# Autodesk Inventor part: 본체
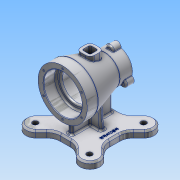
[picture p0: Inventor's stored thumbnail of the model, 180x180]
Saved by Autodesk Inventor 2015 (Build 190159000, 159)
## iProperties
Created: 2018-03
Part Number: 본체
Material: 알루미늄 6061
Document SubType Name: Modeling
Designer: SCD-A03
Density: 2.7 g/cm^3
Appearance: 알루미늄 - 평지
Mass: 1014.9 g
Surface Area: 858.039 cm^2
Volume: 375.89 cm^3
Author: SCD-A03
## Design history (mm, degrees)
sketch "스케치2"
  geometry: C1 r 45 at (0, 0); 1 further point
  constraints: 1 centre point, 1 coincident
  dimensions: "d3" = 90 diameter of C1
extrude "돌출2" new body sketch "스케치2" distance "d4" = 20; taper "d5" = 0 deg
node "작업 평면3"
sketch "스케치3"
  geometry: C1 r 27.5 at (0, 0); 1 further point
  constraints: 1 centre point, 1 coincident
  dimensions: "d9" = 55 diameter of C1
extrude "돌출3" join sketch "스케치3" distance "d10" = 23; taper "d11" = 0 deg
sketch "스케치4"
  geometry: L1 (0, -45)-(-20, -45) reference; L2 (-20, -45)-(-20, 45) reference; L3 (-20, 45)-(0, 45) reference; L4 (0, 45)-(0, -45) reference; L5 (57, 27.5)-(80, 27.5) reference; L6 (80, 27.5)-(80, -27.5) reference; L7 (80, -27.5)-(57, -27.5) reference; L8 (57, -27.5)-(57, 27.5) reference; L9 (0, 45)-(57, 27.5); L10 (57, 27.5)-(57, 0); L11 (57, 0)-(0, 0); L12 (0, 45)-(0, 0)
  constraints: 8 end point, 1 collinear, 1 midpoint, 1 perpendicular
revolve "회전1" sketch "스케치4" stored, may be unused: angle "d12" = 90 deg
node "작업 평면4"
sketch "스케치5"
  geometry: L1 (-12.5, 17.5)-(12.5, 17.5); L2 (12.5, 17.5)-(12.5, 42.5); L3 (12.5, 42.5)-(-12.5, 42.5); L4 (-12.5, 42.5)-(-12.5, 17.5); L5 (-12.5, 17.5)-(12.5, 42.5); L6 (12.5, 17.5)-(-12.5, 42.5); L7 (-45, -20)-(45, -20) reference; 2 further points
  constraints: 12 end point, 2 midpoint, 2 parallel, 1 horizontal, 1 perpendicular
  dimensions: "d14" = 25 distance of L3.end L2.end; "d15" = 25 distance of L2.end L1.end; "d218" = 50 distance from line of point (0, 30) L7
extrude "돌출4" join sketch "스케치5" stored distance "d16" = 23; taper "d17" = 0 deg
sketch "스케치6"
  geometry: L1 (57, -27.5)-(0, -45) reference; L2 (0, -45)-(-20, -45) reference; L3 (-20, -45)-(-20, 45) reference; L4 (-20, 45)-(0, 45) reference; L5 (0, 45)-(17.5, 39.627) reference; L6 (17.5, 39.627)-(17.5, 45) reference; L7 (17.5, 45)-(42.5, 45) reference; L8 (42.5, 45)-(42.5, 31.952) reference; L9 (42.5, 31.952)-(57, 27.5) reference; L10 (57, 27.5)-(80, 27.5) reference; L11 (80, 27.5)-(80, -27.5) reference; L12 (80, -27.5)-(57, -27.5) reference; L13 (-20, 0)-(80, 0); L14 (-20, 35)-(3, 35); L15 (3, 35)-(3, 26); L16 (3, 26)-(50, 26); L17 (50, 26)-(50, 20); L18 (50, 20)-(80, 20); 1 further point
  constraints: 12 end point, 4 perpendicular, 2 midpoint, 2 point on line, 1 horizontal
  dimensions: "d18" = 23 distance of L14.start L14.end; "d19" = 47 distance of L15.end L16.end; "d20" = 35 distance between parallel lines of L13 L14; "d21" = 26 distance between parallel lines of L13 L16; "d22" = 20 distance between parallel lines of L13 L18
revolve "회전2" sketch "스케치6" stored, may be unused: angle "d23" = 90 deg
sketch "스케치7"
  geometry: L1 (-7.5, 22.5)-(7.5, 22.5); L2 (7.5, 22.5)-(7.5, 37.5); L3 (7.5, 37.5)-(-7.5, 37.5); L4 (-7.5, 37.5)-(-7.5, 22.5); L5 (-7.5, 22.5)-(7.5, 37.5); L6 (7.5, 22.5)-(-7.5, 37.5); L7 (-45, -20)-(45, -20) reference; 2 further points
  constraints: 12 end point, 2 midpoint, 2 parallel, 1 horizontal, 1 perpendicular
  dimensions: "d24" = 15 distance of L3.end L2.end; "d25" = 15 distance of L2.end L1.end; "d219" = 50 distance from line of L7 point (0, 30)
extrude "돌출5" cut sketch "스케치7" stored distance "d26" = 23; taper "d27" = 0 deg
node "작업 평면5"
sketch "스케치10"
  geometry: C1 r 35 at (0, 0) reference; 1 further point
  dimensions: "d59" = 40 distance of point (0, 40) C1.centre
hole "구멍2" sketch "스케치10" at (0, 40) diameter "d60" = 3.242; stored, may be unused: countersink angle "d64" = 90 deg, drill point angle "d66" = 118 deg; dims "d61" = 9, "d62" = 4, "d63" = 2, "d65" = 11
sketch "스케치11"
  geometry: C1 r 7 at (0, -27.5); 1 further point
  constraints: 1 centre point, 1 vertical alignment, 1 other
  dimensions: "d70" = 14 diameter of C1
extrude "돌출8" join sketch "스케치11" distance "d71" = 15; taper "d72" = 0 deg
hole "구멍3" diameter "d78" = 3.242; stored, may be unused: countersink angle "d82" = 90 deg, drill point angle "d84" = 118 deg; dims "d76" = 10, "d77" = 10, "d79" = 9, "d80" = 4, "d81" = 2, "d83" = 11
fillet "모깎기1" dims "d88" = 8
fillet "모깎기2" dims "d89" = 3
fillet "모깎기3" dims "d90" = 3
fillet "모깎기4" dims "d91" = 3
node "작업 평면7"
fillet "모깎기8" dims "d135" = 3
fillet "모깎기9" dims "d136" = 1
fillet "모깎기10" dims "d137" = 3
chamfer "모따기5" distance "d143" = 1; stored, may be unused: second distance "d144" = 2, angle "d145" = 45 deg
node "작업 평면10"
sketch "스케치19" dims "d24" = 15, "d25" = 15, "d219" = 50
  geometry: L1 (-26, 47)-(26, 47) reference; L2 (7.5, 25.5)-(7.5, 34.5) reference; L3 (4.5, 37.5)-(-4.5, 37.5) reference; L4 (-7.5, 34.5)-(-7.5, 25.5) reference; L5 (-4.5, 22.5)-(4.5, 22.5) reference; L6 (26, 6)-(-26, 6) reference; L7 (-7.5, 30)-(0, 30); L8 (0, 30)-(0, 37.5); L9 (-45, -15)-(45, -15); L10 (45, -15)-(45, 75); L11 (45, 75)-(-45, 75); L12 (-45, 75)-(-45, -15); L13 (-45, -15)-(45, 75); L14 (45, -15)-(-45, 75); L15 (0, 30)-(49.497, 79.497); L16 (45, -15)-(-45, 75); L17 (45, 75)-(-45, -15); L18 (-45, 75)-(45, -15); L19 (49.497, 79.497)-(31.497, 97.497); L20 (-49.497, 79.497)-(-36.77, 92.225); L21 (-36.77, 92.225)-(62.225, -6.77); L22 (-62.225, 66.77)-(36.77, -32.225); L23 (-36.77, -32.225)-(62.225, 66.77); L24 (-62.225, -6.77)-(36.77, 92.225); L25 (4.5, 22.5)-(-4.5, 22.5) reference; L26 (-7.5, 25.5)-(-7.5, 34.5) reference; L27 (-4.5, 37.5)-(4.5, 37.5) reference; L28 (7.5, 34.5)-(7.5, 25.5) reference; A1 r 18 centre (49.497, 79.497) between (62.225, 66.77) and (36.77, 92.225); A2 r 18 centre (-49.497, 79.497) between (-36.77, 92.225) and (-62.225, 66.77); A3 r 18 centre (-49.497, -19.497) between (-36.77, -32.225) and (-62.225, -6.77); A4 r 18 centre (49.497, -19.497) between (62.225, -6.77) and (36.77, -32.225); 1 further point
  constraints: 36 end point, 8 point on circle, 4 centre point, 4 midpoint, 2 horizontal, 2 parallel, 2 perpendicular, 2 tangent, 1 coincident, 1 point on line, 25 other
  dimensions: "d178" = 90 distance of L11.end L10.end; "d179" = 90 distance of L10.end L9.end; "d180" = 70 distance of L7.end L15.end; "d181" = 36 diameter of A1; "d184" = 360 deg dimension on L7.end L19.start (derived)
extrude "돌출14" join sketch "스케치19" distance "d186" = 12; taper "d187" = 0 deg
sketch "스케치20"
  geometry: L1 (-4, -7)-(4, -7); L2 (4, -7)-(4, 67); L3 (4, 67)-(-4, 67); L4 (-4, 67)-(-4, -7); L5 (-4, -7)-(4, 67); L6 (4, -7)-(-4, 67); L7 (-19.544, -15)-(19.544, -15) reference; 2 further points
  constraints: 12 end point, 2 midpoint, 2 parallel, 1 horizontal, 1 perpendicular
  dimensions: "d188" = 8 distance of L3.end L2.end; "d189" = 74 distance of L2.end L1.end; "d220" = 8 distance between parallel lines of L1 L7
extrude "돌출15" join sketch "스케치20" stored distance "d190" = 12; taper "d191" = 0 deg
node "작업 평면11"
sketch "스케치21"
  geometry: L1 (-3.5, -94.895)-(-3.5, -115) reference; L2 (-3.5, -115)-(-8.5, -115) reference; L3 (-8.5, -115)-(-8.5, -103.536) reference; L4 (0, -34.435)-(0, 0) reference; L5 (0, 0)-(-41, 0) reference; L6 (-41, 0)-(-41, 12) reference; L7 (-41, 12)-(49, 12) reference; L8 (49, 12)-(49, 0) reference; L9 (49, 0)-(8, 0) reference; L10 (8, 0)-(8, -34.435) reference; L11 (16.5, -103.536)-(16.5, -115) reference; L12 (16.5, -115)-(11.5, -115) reference; L13 (11.5, -115)-(11.5, -94.895) reference; L14 (4, 6)-(4, -41.14); L15 (4, 6)-(28, 6); L16 (4, 6)-(28, 6); L17 (28, 6)-(28, 0); L18 (28, 6)-(42.578, 6); L19 (28, 0)-(24.322, -42.041); L20 (28, 0)-(70.201, 0); L21 (24.322, -42.041)-(4, -41.14); L22 (4, 6)-(-20, 6); L23 (-20, 0)-(-16.322, -42.041); L24 (-20, 6)-(-20, 0); L25 (-16.322, -42.041)-(4, -41.14); L26 (4, 6)-(-20, 4.199); L27 (4, 6)-(28, 3); A1 r 26 centre (4, -70) between (11.5, -94.895) and (-3.5, -94.895) reference; A2 r 35.789 centre (4, -70) between (0, -34.435) and (-8.5, -103.536) reference; A3 r 35.789 centre (4, -70) between (16.5, -103.536) and (8, -34.435) reference; 3 further points
  constraints: 28 end point, 4 horizontal, 4 symmetric about line, 2 equal length, 2 point on line, 1 midpoint, 1 vertical
  dimensions: "d192" = 24 distance of L14.start L15.end; "d193" = 0 distance between parallel lines of L15 L16 (derived); "d194" = 90 deg angle of L17 L18; "d195" = 95 deg angle of L19 L20
extrude "돌출16" join sketch "스케치21" stored distance "d196" = 8; taper "d197" = 0 deg
fillet "모깎기15" dims "d198" = 3
fillet "모깎기16" dims "d199" = 3
sketch "스케치22"
  geometry: A1 r 15 centre (-49.497, -20.545) between (-60.104, -9.939) and (-38.891, -31.152) reference; A2 r 15 centre (49.497, -20.545) between (38.891, -31.152) and (60.104, -9.939) reference; A3 r 15 centre (49.497, 78.45) between (60.104, 67.843) and (38.891, 89.056) reference; A4 r 15 centre (-49.497, 78.45) between (-38.891, 89.056) and (-60.104, 67.843) reference; 1 further point
hole "구멍5" sketch "스케치22" at (49.497, 78.45), (-49.497, 78.45), (49.497, -20.545), (-49.497, -20.545) diameter "d203" = 10; stored, may be unused: countersink angle "d207" = 90 deg, drill point angle "d209" = 118 deg; dims "d204" = 6, "d205" = 4, "d206" = 2, "d208" = 8
sketch "스케치23"
  geometry: L1 (19.544, 75)-(-19.544, 75) reference; 2 further points
  constraints: 1 other
  dimensions: "d216" = 45 distance from line of L1 point (35, 30); "d217" = 35 horizontal distance of point (0, 0) point (35, 30)
feature "엠보싱2" sketch "스케치23" dims "d3" = 90, "d13" = 45, "d210" = 0.5, "d211" = 0
fillet "모깎기17" dims "d212" = 25
chamfer "모따기7" distance "d213" = 3; stored, may be unused: second distance "d214" = 2, angle "d215" = 45 deg
fillet "모깎기18" dims "d221" = 1
node "솔리드2"
pattern_circular "원형 패턴1" dims angle "d68" = 360 deg
pattern_circular "원형 패턴2" dims angle "d74" = 360 deg
pattern_circular "원형 패턴3" dims angle "d86" = 360 deg
node "투영된 루프3"
node "절단 모서리 투영1"
node "절단 모서리 투영2"
node "절단 모서리 투영6"
other parameters: "d28" = -82, "d92" = -82, "d177" = -82
